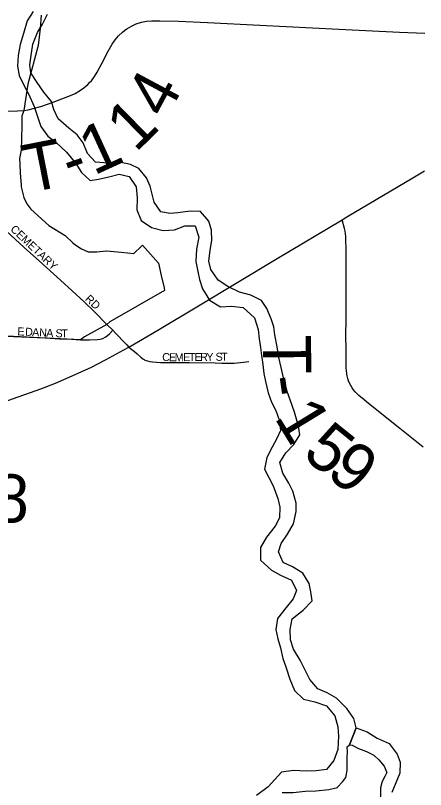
# Model space of a CAD drawing. Extents: x 1584893 to 1934202, y 663575 to 1091909.
# Drawn here: x 1838824 to 1841383, y 956462 to 961295 of the extents above; entities that cross this region are included whole.
import ezdxf

# ---------------------------------------------------------------- set-up
doc = ezdxf.new("R2010")
doc.units = 0
for name, color, linetype in [('GM_X_City_Street', 7, 'Continuous'), ('GM_X_City_Street_Text', 7, 'Continuous'), ('GM_X_Corporation', 7, 'Continuous'), ('GM_X_Major_River', 7, 'Continuous'), ('GM_X_Minor_River', 7, 'Continuous'), ('GM_X_State_Route', 7, 'Continuous'), ('GM_X_Township_Road', 7, 'Continuous'), ('GM_X_Township_Road_Text', 7, 'Continuous'), ('GM_X_Township_Subdivision', 7, 'Continuous'), ('GM_X_Township_Subdivision_Text', 7, 'Continuous')]:
    doc.layers.add(name, color=color, linetype=linetype)

msp = doc.modelspace()

# ---------------------------------------------------------------- linework, layer by layer
at = {"layer": 'GM_X_City_Street'}
for points in [[(1838729.6, 960699.1), (1838770.9, 960698.2), (1838837.2, 960699.6), (1838876.2, 960702.6)], [(1838718.8, 959970.4), (1838726.9, 959969.6), (1838736.7, 959967.5), (1838754.9, 959958.6), (1838767.6, 959947.8), (1838877.8, 959847.4), (1838974.7, 959760.6), (1839105.9, 959641.8), (1839249.6, 959510.3), (1839319.1, 959441.9), (1839394.2, 959366.5)]]:
    msp.add_lwpolyline(points, dxfattribs=at)
at = {"layer": 'GM_X_Corporation'}
msp.add_lwpolyline([(1838984.9, 961297.5), (1838979.1, 961214.4), (1838965.2, 961107.2), (1838900.5, 960865.7), (1838876.2, 960702.6), (1838864.1, 960665.7), (1838863.3, 960611.2), (1838863.3, 960609), (1838863.2, 960607), (1838863.2, 960605), (1838861.9, 960529.8), (1838861.9, 960529.3), (1838861.8, 960527.2), (1838861.8, 960525.2), (1838860.5, 960454.5), (1838849.6, 960402.6), (1838850.3, 960366.4), (1838852.6, 960309.8), (1838858.8, 960237.2), (1838860, 960225.6), (1838872.5, 960176), (1838876.8, 960159.3), (1838894, 960118.6), (1838919.2, 960086.4), (1839032.8, 959983), (1839133.4, 959922.4), (1839182.4, 959875.2), (1839194.2, 959865.3), (1839236.3, 959837.4), (1839277.2, 959818.8), (1839331.4, 959818.8), (1839390, 959826.2), (1839392.4, 959826.4), (1839460, 959819.6), (1839484.6, 959817.1), (1839523.6, 959813.2), (1839561.6, 959809.4), (1839578, 959824.6), (1839595, 959840.3), (1839616.6, 959860.3), (1839716.3, 959748.2), (1839733.5, 959671.8), (1839751, 959594.3), (1839754.8, 959577.4), (1839413.2, 959383.1), (1839394.2, 959366.4), (1839255.4, 959288.1), (1839230.1, 959270.9), (1838729.4, 959294.4)], dxfattribs=at)
at = {"layer": 'GM_X_Major_River'}
for points in [[(1838934.6, 961320.1), (1838897.4, 961262.7), (1838873.7, 961183), (1838854.3, 961113.2), (1838840.8, 961045.3), (1838837.4, 960979.2), (1838846.2, 960920.9), (1838878.8, 960856), (1838905.8, 960805.3), (1838940.1, 960726.4), (1838958.9, 960669.9), (1838981.4, 960601.2), (1839026.1, 960542.2), (1839077.3, 960503), (1839142, 960441.5), (1839200.4, 960370.1)], [(1840495.7, 959033.6), (1840481.1, 959098), (1840468.4, 959160.5), (1840457.8, 959226.9), (1840443.4, 959301.4), (1840436.4, 959351.6), (1840419.5, 959402.1), (1840392.8, 959464.8), (1840359.9, 959515.7), (1840292.6, 959549.2), (1840221.1, 959568.7), (1840149.8, 959602.3), (1840088.7, 959641.7), (1840044.1, 959708.7), (1840031.2, 959761.2), (1840038.7, 959829.2), (1840050, 959891.1), (1840047.3, 959955.3), (1840030.5, 960011.8), (1839977.8, 960071.1), (1839913.9, 960074.4), (1839837.7, 960064), (1839787.6, 960059), (1839731.9, 960070.2), (1839689.1, 960129.3), (1839676.2, 960179.7), (1839665.3, 960230), (1839642.4, 960282.6), (1839593.6, 960339.8), (1839542.2, 960364.9), (1839472.5, 960380.4), (1839402.4, 960373.9), (1839322.6, 960379.5), (1839273.7, 960432.7), (1839247.1, 960499.4), (1839208.2, 960550.4), (1839157.1, 960591.5), (1839090.4, 960649.1), (1839063.6, 960707.8), (1839048.7, 960758.2), (1839000, 960817.4), (1838959.2, 960876.4), (1838920.5, 960937.4), (1838913.6, 960987.7), (1838923.1, 961059.7), (1838932.3, 961115.6), (1838961.8, 961189.2), (1838992.9, 961240.7), (1839024.2, 961304.2)], [(1839200.4, 960370.1), (1839235.3, 960315.2), (1839290.2, 960265.9), (1839342.3, 960272.8), (1839406.6, 960287.6), (1839470.9, 960304.3), (1839532.6, 960290.9), (1839577.2, 960225.8), (1839583.8, 960157.5), (1839582.2, 960081.3), (1839608.8, 960014.6), (1839673.8, 959971.2), (1839745.4, 959953.6), (1839815.4, 959956.2), (1839880, 959982.9), (1839945.9, 959981.5), (1839968.4, 959910.9), (1839952.9, 959837), (1839949.2, 959758.9), (1839961.9, 959696.4), (1839972.8, 959646.1), (1839991.6, 959589.5), (1840034.1, 959518.4), (1840103.2, 959476.9), (1840171.2, 959479.5), (1840245, 959471.9), (1840315.7, 959408.3), (1840338.1, 959335.6), (1840344.9, 959275.3), (1840353.7, 959223), (1840358.7, 959172.8), (1840367.5, 959116.4), (1840374.3, 959060.2), (1840383.2, 959009.8), (1840401.7, 958939.3), (1840422.5, 958880.7), (1840449.4, 958828), (1840470.2, 958771.4), (1840478.8, 958705), (1840455.7, 958653.4), (1840426.6, 958599.9), (1840393.2, 958536.4), (1840377.7, 958462.5), (1840404.6, 958409.8), (1840431.5, 958359.1), (1840461.8, 958280.3), (1840474.6, 958225.9), (1840471.2, 958157.8), (1840444.1, 958106.2), (1840390.7, 958037.1), (1840353.4, 957973.7), (1840353.7, 957893.5), (1840422.4, 957831.9), (1840477.7, 957800.7), (1840547, 957769.2), (1840577.6, 957704.3), (1840556.5, 957652.7), (1840513.4, 957599.4), (1840460, 957530.3), (1840448.5, 957462.4), (1840461.3, 957404), (1840478.1, 957347.5), (1840492.7, 957281), (1840511.6, 957228.5), (1840536, 957151.8), (1840564.5, 957081), (1840621.3, 957025.7), (1840692.9, 957010.1), (1840764.3, 956984.6), (1840817, 956923.3), (1840835.6, 956854.7), (1840840.3, 956796.5), (1840834.6, 956712.4), (1840811.1, 956642.7), (1840764, 956587.5), (1840699.8, 956578.8), (1840637.8, 956576.1), (1840557.9, 956581.8), (1840483.7, 956571.3), (1840399.9, 956478.3)], [(1840949.5, 956847.1), (1840934.6, 956904.8), (1840891.9, 956967.9), (1840827.3, 957033.4), (1840768.1, 957066.7), (1840710.6, 957090), (1840659.8, 957149.2), (1840634.9, 957199.8), (1840600.4, 957270.7), (1840559.9, 957337.8), (1840541.1, 957396.3), (1840538.5, 957460.5), (1840549.9, 957528.5), (1840619, 957583.2), (1840676.2, 957640.1), (1840667.4, 957696.5), (1840656.5, 957748.8), (1840617.9, 957813.8), (1840552.8, 957853.3), (1840495.4, 957880.5), (1840464.8, 957947.3), (1840481.9, 957999.1), (1840521.1, 958056.5), (1840558.4, 958121.9), (1840576, 958197.7), (1840575.1, 958249.8), (1840554.7, 958324.5), (1840529.8, 958375.1), (1840493.1, 958438), (1840474.5, 958504.6), (1840511.8, 958564), (1840560.9, 958617.1), (1840598.1, 958676.5), (1840589.3, 958730.8), (1840565.1, 958817.5), (1840538.8, 958896.3), (1840519.8, 958946.8), (1840495.7, 959033.6)], [(1840907.8, 956741.2), (1840949.5, 956847.1)], [(1840834, 956476.8), (1840865.1, 956510.1), (1840885.5, 956537.9), (1840894.2, 956581.9), (1840894.7, 956621.9), (1840893.3, 956664), (1840895.7, 956698), (1840894.1, 956728.1), (1840907.8, 956741.2)], [(1840399.9, 956478.3), (1840327.1, 956425.2)], [(1840487.3, 956444.1), (1840557.7, 956444.2), (1840631.9, 956451.2), (1840698.1, 956454.3), (1840778.4, 956463.2), (1840832.6, 956474.5), (1840834, 956476.8)]]:
    msp.add_lwpolyline(points, dxfattribs=at)
at = {"layer": 'GM_X_Minor_River'}
for points in [[(1840949.5, 956847.1), (1840907.8, 956741.2)], [(1840949.5, 956847.1), (1841018.8, 956822.8), (1841082, 956783.4), (1841155.2, 956749.8), (1841205.8, 956682.6), (1841224.7, 956632.1), (1841223.3, 956563.9), (1841172.8, 956443.9)], [(1840907.8, 956741.2), (1840924.4, 956739.7), (1840964.1, 956719.1), (1841014, 956700.4), (1841059.7, 956675.8), (1841091.4, 956647.3), (1841124.9, 956608.8), (1841140.4, 956568.5), (1841128, 956542.7), (1841111.6, 956512.8), (1841101, 956472.9)], [(1841101, 956472.9), (1841102, 956398.8), (1841117.2, 956332.5), (1841180.6, 956281.5), (1841246.5, 956264.6), (1841306.6, 956265.8), (1841377, 956286.9), (1841404.8, 956305.6)]]:
    msp.add_lwpolyline(points, dxfattribs=at)
at = {"layer": 'GM_X_State_Route'}
for points in [[(1841302.9, 960282.2), (1841375.4, 960325.5)], [(1838752.9, 958882.6), (1838811.7, 958903.2), (1838981.3, 958964.1), (1839073, 958999.9), (1839178.4, 959045.1), (1839297.5, 959100.1), (1839385.3, 959144.4), (1839500.6, 959207), (1839530.8, 959224.6), (1839712.8, 959330.8), (1839965.8, 959482), (1840457.1, 959777.1), (1840863.1, 960019.7), (1840892.7, 960037.4), (1841302.9, 960282.2)]]:
    msp.add_lwpolyline(points, dxfattribs=at)
at = {"layer": 'GM_X_Township_Road'}
for points in [[(1838876.2, 960702.6), (1838902.8, 960706.9), (1838934.6, 960714.1), (1838981.6, 960727.8), (1839059, 960754.8), (1839166.5, 960795.4), (1839195.9, 960809.1), (1839223.9, 960825.3), (1839250.5, 960844), (1839275.4, 960864.8), (1839286.9, 960876.1), (1839297.7, 960888), (1839317.3, 960913.8), (1839334.6, 960941.2), (1839365.6, 960998.9), (1839403, 961072.3), (1839427.8, 961115.4), (1839446.6, 961142.8), (1839467.9, 961168.4), (1839491.9, 961191.7), (1839504.9, 961202.3), (1839518.5, 961212.1), (1839532.6, 961221), (1839547.3, 961229), (1839577.9, 961242.5), (1839609.8, 961252.5), (1839642.5, 961258.8), (1839675.7, 961261.8), (1839725.4, 961262.6), (1839840.6, 961258.8), (1840021.3, 961250.6), (1840349.6, 961234.4), (1840842.3, 961210.5), (1841219.9, 961192), (1841378.8, 961184.4)], [(1840891.9, 959056.4), (1840891.2, 959060.6), (1840888.3, 959093), (1840886.7, 959217.7), (1840886.3, 959289.9), (1840886.8, 959405.1), (1840886.8, 959569.5), (1840887.1, 959816.2), (1840885.6, 959915.2), (1840882.3, 959948.4), (1840877.8, 959965), (1840863.1, 960019.7)], [(1841000.7, 958894.5), (1840967, 958923), (1840944.1, 958945.8), (1840933.7, 958958.2), (1840924.2, 958971.1), (1840915.8, 958984.7), (1840908.6, 958998.9), (1840902.4, 959013.7), (1840897.6, 959029.2), (1840893.9, 959044.7), (1840891.9, 959056.4)], [(1841367.5, 958600.8), (1841222.9, 958716.9), (1841017, 958880.7), (1841000.7, 958894.5)]]:
    msp.add_lwpolyline(points, dxfattribs=at)
at = {"layer": 'GM_X_Township_Subdivision'}
for points in [[(1839394.2, 959366.5), (1839430.8, 959330.4)], [(1838729.4, 959294.4), (1838747.5, 959293.5), (1838768.2, 959292.5), (1838812.5, 959290.8), (1839008.7, 959282.2), (1839098.1, 959277), (1839172.8, 959274.4), (1839230.1, 959270.9)], [(1839230.1, 959270.9), (1839285.7, 959270.4), (1839336.6, 959271.2), (1839353.4, 959273.3), (1839369.6, 959278.3), (1839384.6, 959285.9), (1839398, 959296.3), (1839409.8, 959308.5), (1839430.8, 959330.4)], [(1839430.8, 959330.4), (1839448.8, 959312.6), (1839468.8, 959291.8), (1839490, 959268.4), (1839501.9, 959254.9), (1839518, 959238), (1839530.8, 959224.6)], [(1839530.8, 959224.6), (1839550.4, 959208.9), (1839565.9, 959196.5), (1839582.4, 959183.3), (1839606, 959162.3), (1839618.5, 959152), (1839627.3, 959146.6)], [(1839627.3, 959146.6), (1839632.3, 959143.6), (1839647.5, 959138.3), (1839663.4, 959135.1), (1839679.6, 959133), (1839728.2, 959129.5), (1839776.9, 959127.9), (1839906.9, 959127.8), (1840069.3, 959125.9), (1840112.2, 959124.3), (1840187.8, 959125.2), (1840246.8, 959130.4), (1840279.8, 959134.8)]]:
    msp.add_lwpolyline(points, dxfattribs=at)

# ---------------------------------------------------------------- texts
at = {"layer": 'GM_X_City_Street_Text'}
for s, rotation, p in [('CEMETARY', 316.6051, (1838788, 959955.9)), ('RD', 317.1283, (1839254.4, 959520.4))]:
    msp.add_text(s, height=50, rotation=rotation, dxfattribs=at).set_placement(p)
at = {"layer": 'GM_X_Township_Road_Text'}
for s, rotation, p in [('4', 61.8156, (1839764.4, 960643)), ('1', 44.3691, (1839572.7, 960434.5)), ('1', 24.5871, (1839312, 960294)), ('T', 11.1225, (1838902.5, 960186.7)), ('-', 19.2071, (1839167.2, 960242)), ('T', 270.3257, (1840368.5, 959301.8)), ('-', 278.1333, (1840373, 959033)), ('1', 301.4285, (1840435.2, 958786.8)), ('5', 321.1588, (1840605.5, 958544.9)), ('9', 322.0863, (1840753.6, 958425.7)), ('8', 358.2566, (1838681.3, 958133.5))]:
    msp.add_text(s, height=300, rotation=rotation, dxfattribs=at).set_placement(p)
at = {"layer": 'GM_X_Township_Subdivision_Text'}
for s, rotation, p in [('E', 357.1581, (1838834.9, 959298.5)), ('D', 357.1556, (1838883.2, 959296.1)), ('A', 357.1556, (1838927.1, 959293.9)), ('N', 357.1556, (1838971.1, 959291.7)), ('A', 357.1556, (1839015, 959289.5)), ('S', 358.135, (1839073.1, 959286.7)), ('T', 359.7191, (1839109.8, 959285.5)), ('C', 354.9903, (1839737.7, 959140)), ('E', 359.769, (1839781.7, 959136.3)), ('M', 0.6136, (1839817.7, 959136.2)), ('E', 0.6484, (1839870.5, 959136.8)), ('T', 0.6484, (1839905.7, 959137.2)), ('E', 0.6484, (1839940.9, 959137.6)), ('R', 0.6315, (1839976.1, 959138)), ('Y', 0.6462, (1840015.8, 959138.4)), ('S', 0.6484, (1840072.9, 959139.1)), ('T', 0.6557, (1840108.1, 959139.5))]:
    msp.add_text(s, height=50, rotation=rotation, dxfattribs=at).set_placement(p)

doc.saveas('drawing.dxf')
